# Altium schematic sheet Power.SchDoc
size A3; SheetNumber: 3; SheetTotal: 4
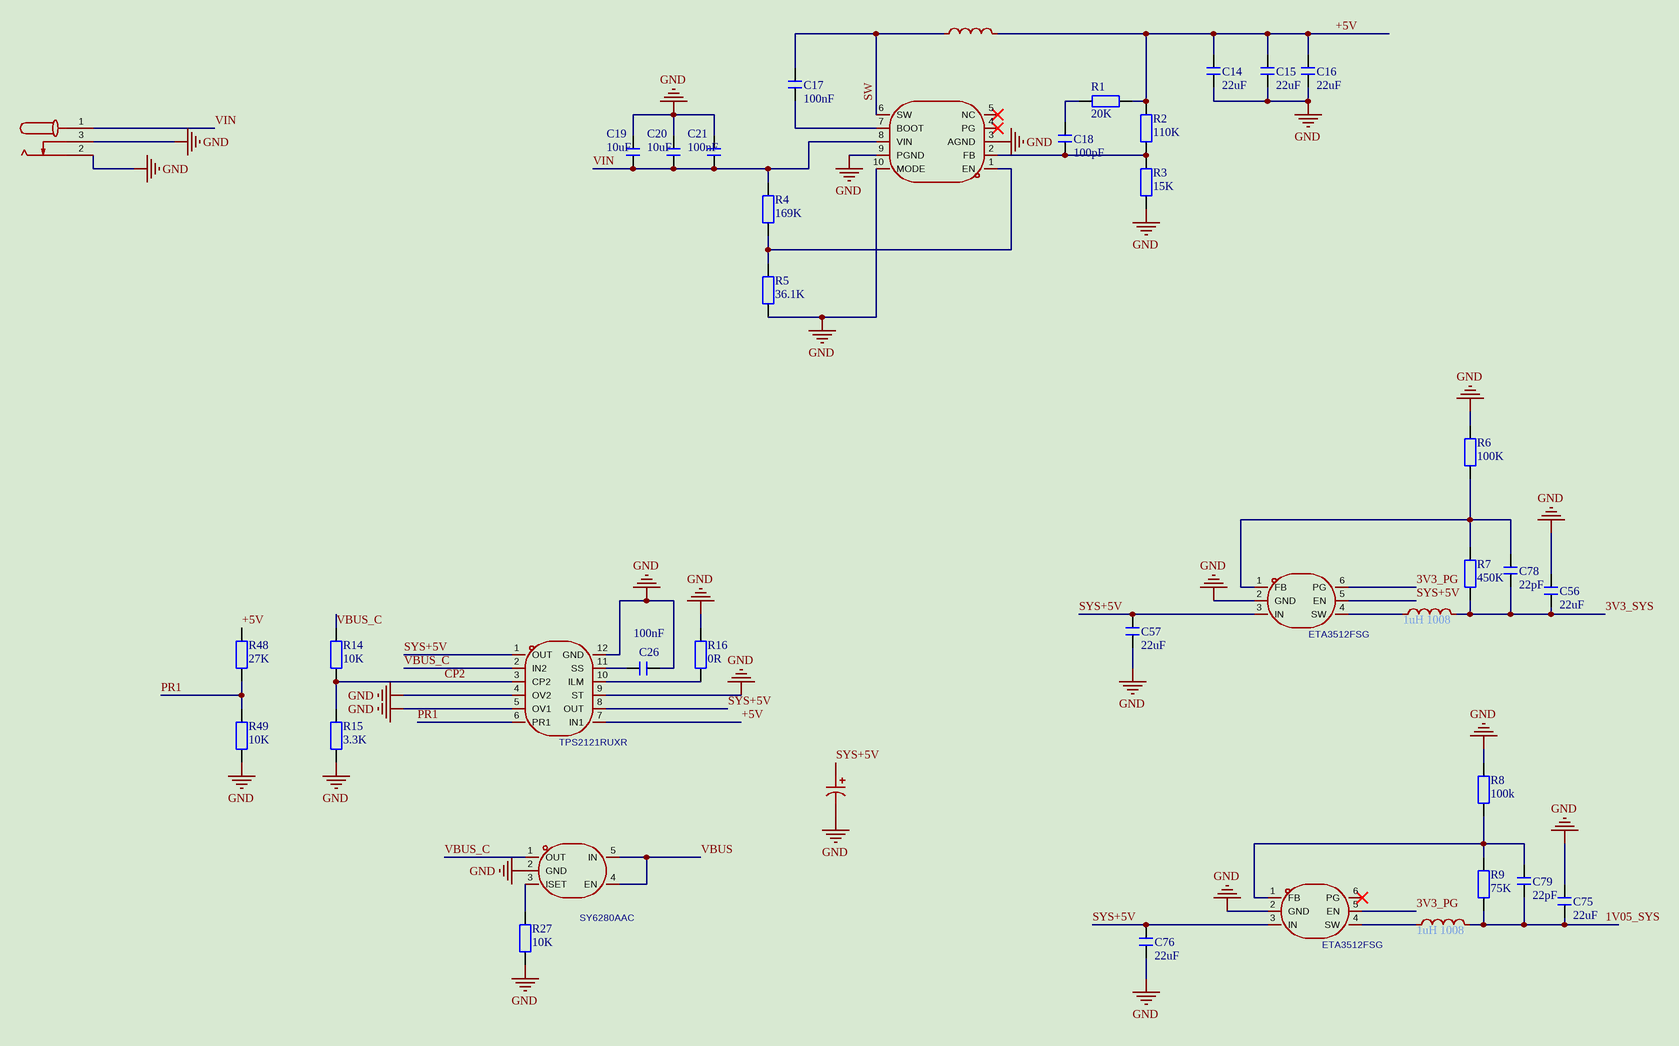
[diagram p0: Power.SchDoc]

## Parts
C14  22uF  [C 0805_L]
C15  22uF  [C 0805_L]
C16  22uF  [C 0805_L]
C17  100nF  [C 0603_L]
C18  100pF  [C 0603_L]
C19  10uF  [C 0805_L]
C20  10uF  [C 0805_L]
C21  100nF  [C 0603_L]
C26  100nF  [C 0603_L]
C37  ma25v220m6x8  [CAP-SMD_BD6.3-L6.6-W6.6-LS7.3-FD]  (value not drawn)
C56  22uF  [C 0603_L]
C57  22uF  [C 0603_L]
C75  22uF  [C 0603_L]
C76  22uF  [C 0603_L]
C78  22pF  [C 0402_L]
C79  22pF  [C 0402_L]
DC1  dc-005-a200  [DC-IN-TH_DC-005-A200]  (value not drawn)
L2  pcr0630-3r3-m  [IND-SMD_L7.5-W6.6]  (value not drawn)
R1  20K  [R 0603_L]
R2  110K  [R 0603_L]
R3  15K  [R 0603_L]
R4  169K  [R 0603_L]
R5  36.1K  [R 0603_L]
R6  100K  [R 0402_L]
R7  450K  [R 0402_L]
R8  100k  [R 0402_L]
R9  75K  [R 0402_L]
R14  10K  [R 0603_L]
R15  3.3K  [R 0603_L]
R16  0R  [R 0603_L]
R27  10K  [R 0603_L]
R48  27K  [R 0603_L]
R49  10K  [R 0603_L]
U2  tps56637rpar  [VQFN-HR-10_L3.0-W3.0_RPA]  (value not drawn)
U4  ftc252012s1r0mbca  [IND-SMD_L2.5-W2.0-VLS252012CX-150M]  (value not drawn)
U5  ftc252012s1r0mbca  [IND-SMD_L2.5-W2.0-VLS252012CX-150M]  (value not drawn)
U13  tps2121ruxr  [VQFN-HR-12_L2.5-W2.0-P0.50-BL]
U14  Symbol: SY6280AAC  [SOT-23-5_L3.0-W1.7-P0.95-LS2.8-BL]  (hidden comment: sy6280aac_c55136)
U17  eta3512fsg  [SOT-563-6_L1.6-W1.2-P0.5-LS1.6-BL]
U19  eta3512fsg  [SOT-563-6_L1.6-W1.2-P0.5-LS1.6-BL]

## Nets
GND: C14.1 C15.1 C16.1 C19.2 C20.2 C21.2 C26.1 C37.2 C56.1 C57.1 C75.1 C76.1 DC1.2 DC1.3 R3.1 R5.1 R6.2 R8.2 R15.1 R16.1 R27.2 R49.1 U2.3(AGND) U2.9(PGND) U2.10(MODE) U13.4(OV2) U13.5(OV1) U13.9(ST) U13.12(GND) U14.2(GND) U17.2(GND) U19.2(GND)
1V05_SYS: C75.2 C79.1 R9.1 U5.2
3V3_PG: U17.6(PG) U19.5(EN)
3V3_SYS: C56.2 C78.1 R7.1 U4.2
+5V: C14.2 C15.2 C16.2 L2.2 R1.1 R2.2 R48.2 U13.7(IN1)
CP2: R14.1 R15.2 U13.3(CP2)
PR1: R48.1 R49.2 U13.6(PR1)
SW: C17.2 L2.1 U2.6(SW)
SYS+5V: C37.1 C57.2 C76.2 U13.1(OUT) U13.8(OUT) U17.3(IN) U17.5(EN) U19.3(IN)
VBUS: U14.4(EN) U14.5(IN)
VBUS_C: R14.2 U13.2(IN2) U14.1(OUT)
VIN: C19.1 C20.1 C21.1 DC1.1 R4.2 U2.8(VIN)
NetC17_1: C17.1 U2.7(BOOT)
NetC18_1: C18.1 R2.1 R3.2 U2.2(FB)
NetC18_2: C18.2 R1.2
NetC26_2: C26.2 U13.11(SS)
NetC78_2: C78.2 R6.1 R7.2 U17.1(FB)
NetC79_2: C79.2 R8.1 R9.2 U19.1(FB)
NetR4_1: R4.1 R5.2 U2.1(EN)
NetR16_2: R16.2 U13.10(ILM)
NetR27_1: R27.1 U14.3(ISET)
NetU4_1: U4.1 U17.4(SW)
NetU5_1: U5.1 U19.4(SW)

Not connected (* = marked no-connect by the designer): U2 4(PG)* 5(NC)*; U19 6(PG)*

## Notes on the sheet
- (near U4) 1uH 1008
- (near U5) 1uH 1008

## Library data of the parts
C14-C21 C26 C56 C57 C75 C76 C78 C79 = C: 无极性贴片电容; 版权归属: 源创客; 材质: X7R
C37 = ma25v220m6x8: 容值:220uF;精度:±20%;额定电压:25V;纹波电流:2.9A@100kHz;等效串联电阻(ESR):28mΩ@100kHz;类型:聚合物;; Manufacturer: JIERR(捷而瑞); AddInBom: yes; ModelId: 697a8c63e3274188b68c96045bc3ea1c; ModelTransform: 287.401,259.842,0,180,0,0,0.001,0.001,0; Value: 220uF; Tolerance: ±20%; Voltage Rating: 25V; Type: 聚合物; Lifetime: 2000hrs@105℃
DC1 = dc-005-a200: 连接器类型:DC电源插座;安装方式:弯插;触点内径:2mm;触点外径:6.4mm;额定电流:3A;额定电压:30V;工作温度:-20℃~+70℃;; Manufacturer: XUNPU(讯普); AddInBom: yes; ModelId: 1321cdbe1dc84555a9684967491c8670; ModelTransform: 553.149,368.14887,0,0,0,0,-137.795,85.63,-161.417; Connector Type: DC电源插座; Inside Contact Diameter: 2mm; Outside Contact Diameter: 6.4mm; Current Rating: 3A; Voltage Rating (Max): 30V
L2 = pcr0630-3r3-m: 合金电感 一体成型电感 大电流; Manufacturer: JIERR(捷而瑞); AddInBom: yes; ModelId: c59904d920804e3c81522e1ce8ef9eb5; ModelName: IND-SMD_L7.5-W6.6-H3.0; ModelTransform: 295.275,259.842,0,0,0,0,0,0,0
R1-R9 R14-R16 R27 R48 R49 = R: 贴片电阻; 版权归属: 源创客
U2 = tps56637rpar: 功能类型:降压型;输出类型:可调;输入电压:4.5V~28V;输出电压:600mV~13V;输出电流(最大值):6A;; Manufacturer: TI(德州仪器); AddInBom: yes; ModelId: 5db67d97db7a4d23a493647eeeda17db; ModelTransform: 118.8974,118.8974,0,0,0,0,1.575,0,0; Function: 降压型; Output Type: 可调; Output Current (Max): 6A; Switching Frequency: 500kHz; Synchronous Rectification: 是; Number of Outputs: 1; Topology: 降压式; Switch tube (built-in/external): 内置
U4 U5 = ftc252012s1r0mbca: 小型化一体成型T-CORE，小体积，扁线工艺，感值小; Manufacturer: cjiang(长江微电); AddInBom: yes; ModelId: e143e04106934774881cec608355723f; ModelTransform: 98.504,78.819,0,0,0,0,-0.004,-0.003,0
U13 = tps2121ruxr: TPS2121 支持无缝切换的 2.7V 至 22V、56mΩ、4.5A 电源多路复用器; Manufacturer: TI(德州仪器); AddInBom: yes; ModelId: 23ed45b0241644698956addf625daed0; ModelName: VQFN-HR-12_L2.5-W2.0-H1.0-P0.50-BL; ModelTransform: 78.74,98.425,0,90,0,0,-0.004,0.002,0
U14 = sy6280aac_c55136: 类型:高侧开关;通道数:1;输入控制逻辑:高电平有效;工作电压:2.4V~5.5V;最大连续电流:2A;导通电阻:80mΩ;; Manufacturer: Silergy(矽力杰); AddInBom: yes; ModelId: 0a2a1b8f50944f73965918ad6e5fe167; ModelName: SOT-23-5_L2.9-W1.6-H1.1-LS2.8-P0.95; ModelTransform: 118.60433,114.173,0,90,0,0,0.0005,0.0005,0; Number of Channels: 1; Control Input Logic: 高电平有效; Maximum Continuous Current: 2A; RDS(on): 80mΩ
U17 U19 = eta3512fsg: 功能类型:降压型;工作电压:2.5V~5.5V;输出电压:600mV~5.5V;输出电流:3A;输出类型:可调;; Manufacturer: ETA(钰泰); AddInBom: yes; ModelId: 6c48915c55ca481897faee5dfab5b527; ModelTransform: 62.992,62.992,0,0,0,0,0,0,0; Function: 降压型; Output Current: 3A; Frequency - Switching: 2MHz; Synchronous Rectifier: 是; Number of Outputs: 1; Topology: 降压式; Quiescent Current: 50uA; Switch tube (built-in/external): 内置; Output Type: 可调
